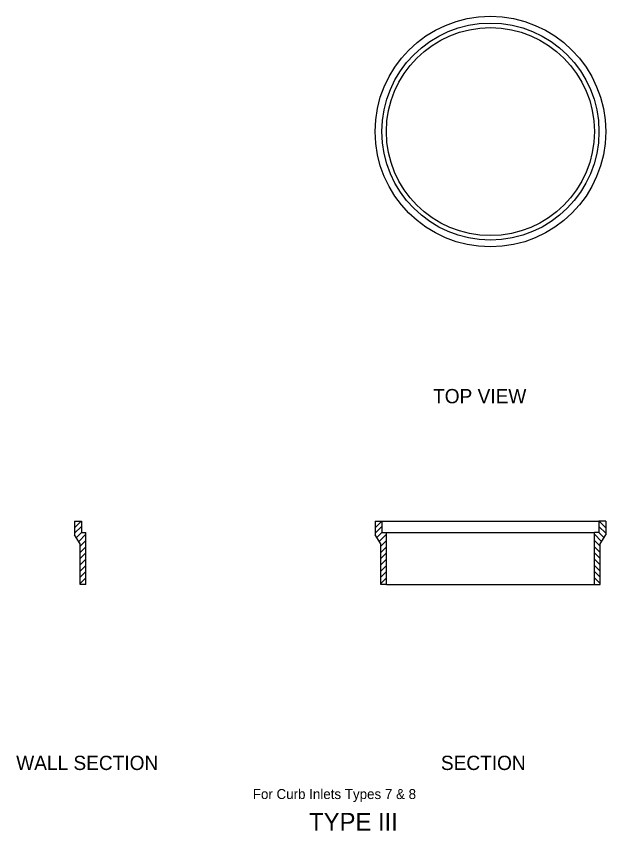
# Model space of a CAD drawing. Extents: x 4851 to 4902, y 9954.5 to 9971.9.
# Drawn here: x 4883.87 to 4889.31, y 9963.8 to 9971.31 of the extents above; entities that cross this region are included whole.
import ezdxf

# ---------------------------------------------------------------- set-up
doc = ezdxf.new("R2010")
doc.units = 0
for name, color, linetype in [('Dimension', 7, 'Continuous'), ('DSText', 7, 'Continuous'), ('SupstrConc', 7, 'Continuous'), ('TextMisc', 7, 'Continuous')]:
    doc.layers.add(name, color=color, linetype=linetype)

msp = doc.modelspace()

# ---------------------------------------------------------------- linework, layer by layer
at = {"layer": 'Dimension'}
for p, q in [((4884.411, 9966.657), (4884.4735, 9966.657)), ((4884.411, 9966.657), (4884.411, 9966.532)), ((4884.4735, 9966.657), (4884.4735, 9966.5528)), ((4887.1801, 9966.657), (4887.2426, 9966.657)), ((4887.1801, 9966.657), (4887.1801, 9966.532)), ((4887.2426, 9966.657), (4887.2426, 9966.5528)), ((4889.3051, 9966.657), (4889.2426, 9966.657)), ((4889.2426, 9966.657), (4889.2426, 9966.5528)), ((4889.3051, 9966.657), (4889.3051, 9966.532)), ((4884.4631, 9966.4486), (4884.411, 9966.532)), ((4884.4735, 9966.5528), (4884.5152, 9966.5528)), ((4884.5152, 9966.0736), (4884.5152, 9966.5528)), ((4887.2322, 9966.4486), (4887.1801, 9966.532)), ((4887.2426, 9966.5528), (4887.2843, 9966.5528)), ((4887.2843, 9966.0736), (4887.2843, 9966.5528)), ((4889.2426, 9966.5528), (4889.2009, 9966.5528)), ((4889.2009, 9966.0736), (4889.2009, 9966.5528)), ((4889.253, 9966.4486), (4889.3051, 9966.532)), ((4884.4631, 9966.0736), (4884.4631, 9966.4486)), ((4887.2322, 9966.0736), (4887.2322, 9966.4486)), ((4889.253, 9966.0736), (4889.253, 9966.4486)), ((4884.5152, 9966.0736), (4884.4631, 9966.0736)), ((4887.2843, 9966.0736), (4887.2322, 9966.0736)), ((4889.2009, 9966.0736), (4889.253, 9966.0736))]:
    msp.add_line(p, q, dxfattribs=at)
for radius in [1.0625, 1, 0.9583]:
    msp.add_circle((4888.2426, 9970.2468), radius, dxfattribs=at)
at = {"layer": 'SupstrConc'}
for p, q in [((4887.2426, 9966.657), (4889.2426, 9966.657)), ((4887.2843, 9966.5528), (4889.2009, 9966.5528)), ((4887.2843, 9966.0736), (4889.2009, 9966.0736))]:
    msp.add_line(p, q, dxfattribs=at)
at = {"layer": 'TextMisc'}
for points in [[(4884.411, 9966.5952), (4884.4722, 9966.6564)], [(4884.411, 9966.5463), (4884.4735, 9966.6088)], [(4887.1801, 9966.5952), (4887.2413, 9966.6564)], [(4887.1801, 9966.5463), (4887.2426, 9966.6088)], [(4889.3051, 9966.5463), (4889.2426, 9966.6088)], [(4889.3051, 9966.5952), (4889.2438, 9966.6564)], [(4884.4273, 9966.5054), (4884.474, 9966.5521)], [(4884.4494, 9966.4703), (4884.5152, 9966.536)], [(4887.1964, 9966.5054), (4887.2431, 9966.5521)], [(4887.2185, 9966.4703), (4887.2843, 9966.536)], [(4889.2666, 9966.4703), (4889.2009, 9966.536)], [(4889.2887, 9966.5054), (4889.242, 9966.5521)], [(4884.4631, 9966.4266), (4884.5155, 9966.4791)], [(4887.2322, 9966.4266), (4887.2846, 9966.4791)], [(4889.253, 9966.4266), (4889.2005, 9966.4791)], [(4884.4631, 9966.3693), (4884.5152, 9966.4214)], [(4884.4631, 9966.3121), (4884.5152, 9966.3642)], [(4887.2322, 9966.3693), (4887.2843, 9966.4214)], [(4887.2322, 9966.3121), (4887.2843, 9966.3642)], [(4889.253, 9966.3693), (4889.2009, 9966.4214)], [(4889.253, 9966.3121), (4889.2009, 9966.3642)], [(4884.4631, 9966.2548), (4884.5152, 9966.3069)], [(4887.2322, 9966.2548), (4887.2843, 9966.3069)], [(4889.253, 9966.2548), (4889.2009, 9966.3069)], [(4884.4631, 9966.1976), (4884.5152, 9966.2497)], [(4887.2322, 9966.1976), (4887.2843, 9966.2497)], [(4889.253, 9966.1976), (4889.2009, 9966.2497)], [(4884.4631, 9966.1403), (4884.5152, 9966.1924)], [(4884.4631, 9966.0831), (4884.5152, 9966.1352)], [(4887.2322, 9966.1403), (4887.2843, 9966.1924)], [(4887.2322, 9966.0831), (4887.2843, 9966.1352)], [(4889.253, 9966.1403), (4889.2009, 9966.1924)], [(4889.253, 9966.0831), (4889.2009, 9966.1352)], [(4884.5109, 9966.0737), (4884.5152, 9966.0779)], [(4887.28, 9966.0737), (4887.2843, 9966.0779)], [(4889.2051, 9966.0737), (4889.2009, 9966.0779)]]:
    msp.add_lwpolyline(points, dxfattribs=at)

# ---------------------------------------------------------------- texts
at = {"layer": 'DSText'}
for s, height, p in [('TOP VIEW', 0.13144, (4887.7144, 9967.7432)), ('WALL SECTION', 0.131438, (4883.8731, 9964.3638)), ('SECTION', 0.13144, (4887.7865, 9964.3638)), ('For Curb Inlets Types 7 & 8', 0.092007, (4886.0532, 9964.0963)), ('TYPE III', 0.1643, (4886.572, 9963.8044))]:
    msp.add_text(s, height=height, dxfattribs=at).set_placement(p)

doc.saveas('drawing.dxf')
